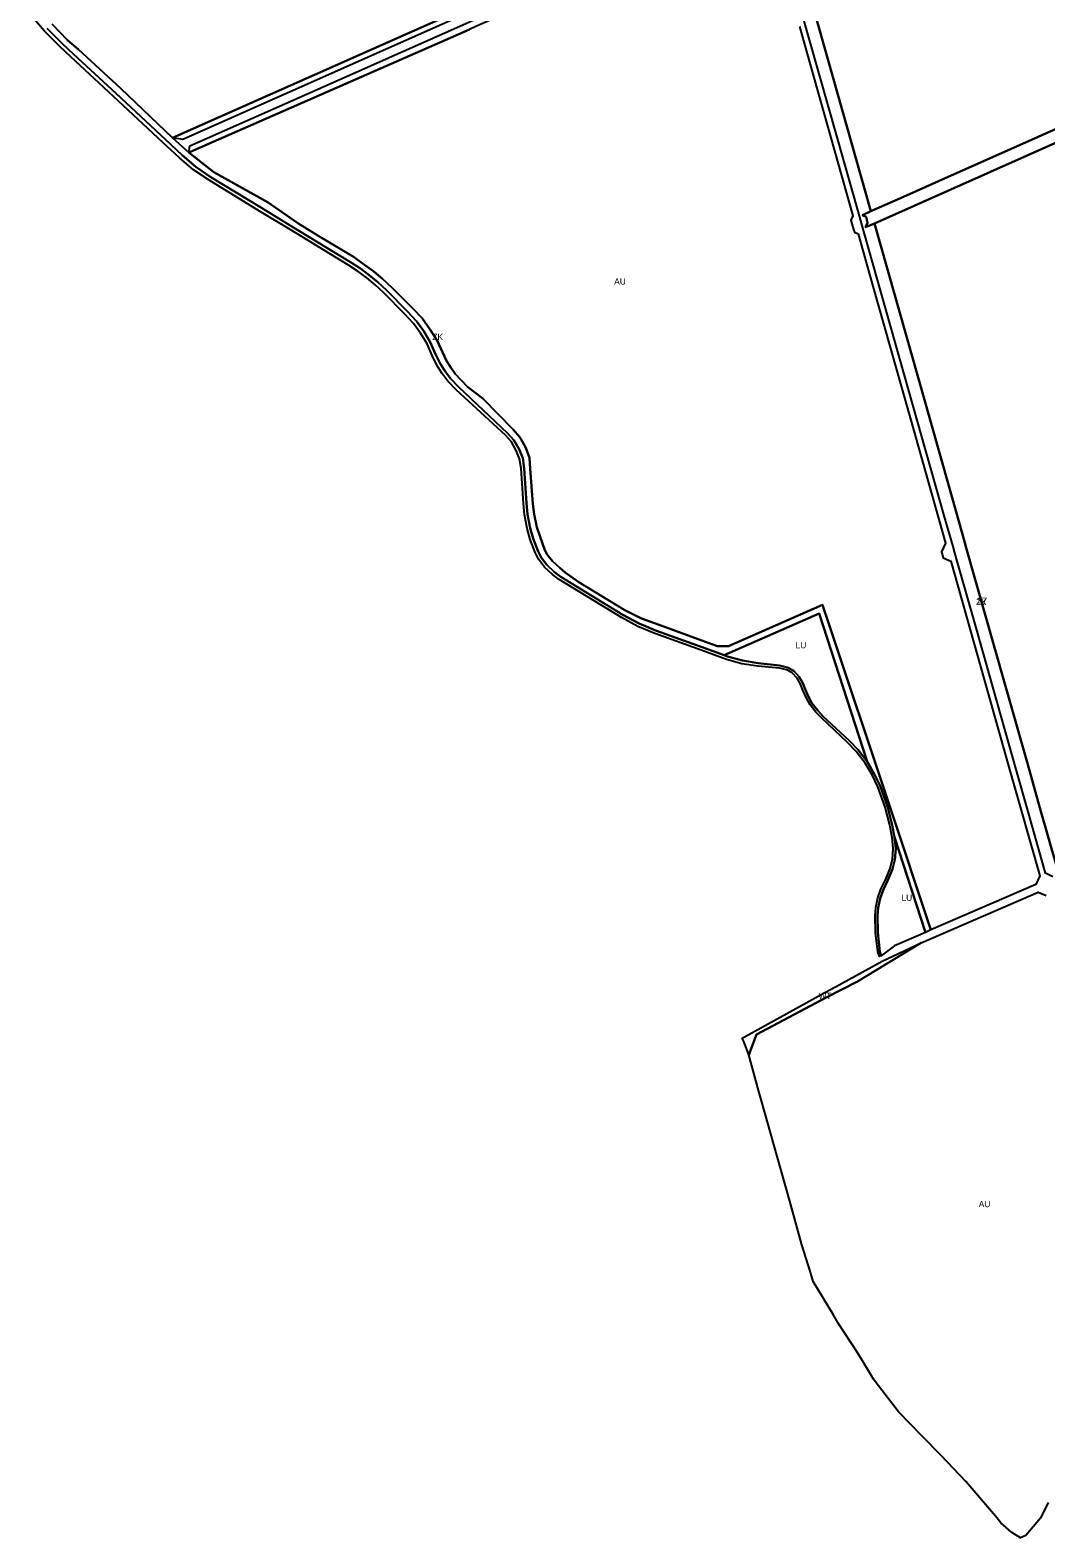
# Model space of a CAD drawing. Extents: x -522079 to -518833, y -1142398 to -1139961.
# Drawn here: x -521819 to -521003, y -1142398 to -1141186 of the extents above; entities that cross this region are included whole.
import ezdxf

# ---------------------------------------------------------------- set-up
doc = ezdxf.new("R2010")
doc.units = 0
for name, color, linetype in [('90640013', 7, 'Continuous'), ('90710013', 7, 'Continuous'), ('90710023', 7, 'Continuous'), ('90750013', 7, 'Continuous'), ('90770013', 7, 'Continuous'), ('ID_navrh', 7, 'Continuous')]:
    doc.layers.add(name, color=color, linetype=linetype)

msp = doc.modelspace()

# ---------------------------------------------------------------- linework, layer by layer
at = {"layer": '90640013'}
msp.add_lwpolyline([(-521805.87, -1141184.18), (-521793.6, -1141196.53), (-521784.67, -1141204.85), (-521750.42, -1141236.56), (-521710.79, -1141273.6), (-521697.27, -1141286.12), (-521686.23, -1141295.55), (-521674.08, -1141303.65), (-521633.59, -1141328.38), (-521608.95, -1141343.32), (-521561.83, -1141372.1), (-521553.85, -1141377.26), (-521546.79, -1141382.47), (-521539.97, -1141388.19), (-521532.97, -1141394.62), (-521516.02, -1141411.74), (-521508.94, -1141419.63), (-521503.06, -1141427.66), (-521497.72, -1141436.55), (-521493.43, -1141445.97), (-521489.81, -1141453.49), (-521485.96, -1141459.56), (-521481.44, -1141465.72), (-521474.82, -1141472.48), (-521435.7, -1141509.5), (-521430.56, -1141515.15), (-521426.4, -1141522.52), (-521423.45, -1141529.64), (-521422.3, -1141537.87), (-521420.36, -1141565.98), (-521419.55, -1141574.63), (-521417.39, -1141585.84), (-521415, -1141594.31), (-521411.13, -1141604.62), (-521408.6, -1141609.5), (-521404.06, -1141615.52), (-521397.79, -1141621.36), (-521392.9, -1141624.99), (-521342.84, -1141655.56), (-521329.77, -1141662.64), (-521315.94, -1141668.52), (-521279.18, -1141681.72), (-521261.42, -1141688.16), (-521258.87, -1141689.08), (-521246.75, -1141692.49), (-521234.23, -1141694.42), (-521216.85, -1141696.44), (-521210.58, -1141697.9), (-521205.36, -1141700.71), (-521201.07, -1141705.38), (-521198.1, -1141710.58), (-521196.27, -1141715.36), (-521193.87, -1141721.1), (-521191.06, -1141726.58), (-521186.22, -1141732.52), (-521181.74, -1141737.31), (-521160.88, -1141756.78), (-521153.73, -1141764.26), (-521146.44, -1141773.64), (-521140.73, -1141783.35), (-521136, -1141793.25), (-521130, -1141809.79), (-521126.54, -1141823.43), (-521124.58, -1141834.32), (-521123.46, -1141843.47), (-521124.12, -1141852.65), (-521126.12, -1141860.01), (-521130.11, -1141869.48), (-521133.7, -1141876.9), (-521136.12, -1141883.81), (-521137.56, -1141891.19), (-521138.09, -1141897.36), (-521137.83, -1141911.01), (-521136.31, -1141926.58), (-521135.11, -1141929.87), (-521136.46, -1141930.46), (-521137.86, -1141926.67), (-521139.81, -1141911.29), (-521140.05, -1141897.31), (-521139.56, -1141890.84), (-521138.03, -1141883.29), (-521135.49, -1141876.13), (-521131.82, -1141868.6), (-521127.98, -1141859.55), (-521126.1, -1141852.28), (-521125.45, -1141843.51), (-521126.47, -1141834.73), (-521128.54, -1141823.8), (-521131.96, -1141810.32), (-521137.85, -1141793.99), (-521142.46, -1141784.23), (-521148.13, -1141774.78), (-521155.26, -1141765.5), (-521162.29, -1141758.22), (-521183.03, -1141738.83), (-521187.74, -1141733.86), (-521192.28, -1141728.07), (-521195.55, -1141722.03), (-521198.13, -1141716.1), (-521199.97, -1141711.28), (-521202.67, -1141706.57), (-521206.66, -1141702.29), (-521211.3, -1141699.75), (-521216.85, -1141698.47), (-521234.47, -1141696.96), (-521247.24, -1141694.95), (-521259.69, -1141691.44), (-521280.03, -1141684.05), (-521317.08, -1141670.75), (-521330.81, -1141664.89), (-521344.1, -1141657.73), (-521394.19, -1141627.12), (-521399.42, -1141623.32), (-521405.95, -1141617.2), (-521410.67, -1141610.84), (-521413.41, -1141605.57), (-521417.34, -1141595.15), (-521419.85, -1141586.36), (-521421.99, -1141574.92), (-521422.84, -1141566.15), (-521424.81, -1141537.99), (-521425.94, -1141530.31), (-521428.59, -1141523.58), (-521432.52, -1141516.64), (-521437.41, -1141511.31), (-521476.9, -1141474.65), (-521483.59, -1141467.79), (-521488.42, -1141461.33), (-521492.43, -1141454.93), (-521496.24, -1141447.12), (-521500.39, -1141437.89), (-521505.54, -1141429.29), (-521511.22, -1141421.52), (-521518.22, -1141413.8), (-521535.13, -1141396.73), (-521541.97, -1141390.39), (-521548.66, -1141384.81), (-521555.61, -1141379.71), (-521563.41, -1141374.64), (-521610.54, -1141345.88), (-521635.13, -1141330.98), (-521675.66, -1141306.27), (-521688.05, -1141297.92), (-521699.37, -1141288.32), (-521712.83, -1141275.84), (-521752.44, -1141238.81), (-521786.69, -1141207.07), (-521795.61, -1141198.73), (-521808.03, -1141186.29), (-521819.49, -1141173.11)], dxfattribs=at)
msp.add_lwpolyline([(-521241.65, -1142009.35), (-521245.74, -1141998.54), (-521247.07, -1141995.86), (-521180.62, -1141959.39), (-521171.94, -1141954.7), (-521134.44, -1141933.97), (-521103.17, -1141919.44), (-521154.29, -1141950.51), (-521178.81, -1141962.98), (-521235.48, -1141993.03)], close=True, dxfattribs=at)
at = {"layer": '90710013'}
for points in [[(-521801.69, -1141180.84), (-521789.46, -1141193.57), (-521780.54, -1141201.02), (-521746.52, -1141232.38), (-521705, -1141272.16), (-521692.02, -1141284.07), (-521671.77, -1141299.69), (-521628.15, -1141324.02), (-521604.24, -1141340.75), (-521587.36, -1141351.16), (-521558.92, -1141368.2), (-521557.71, -1141369.1), (-521550.74, -1141374.27), (-521543.06, -1141379.52), (-521536.29, -1141385.49), (-521528.31, -1141392.77), (-521511.47, -1141409.59), (-521504.19, -1141417.07), (-521498.23, -1141425.96), (-521492.17, -1141435.06), (-521488.03, -1141444.36), (-521484.69, -1141451.44), (-521481.18, -1141456.84), (-521477.75, -1141461.99), (-521467.85, -1141472.41), (-521455.62, -1141481.81), (-521431.09, -1141506.63), (-521426.04, -1141512.48), (-521425.07, -1141514.17), (-521421, -1141521.26), (-521418.07, -1141529.55), (-521417.47, -1141538.2), (-521415.34, -1141566.3), (-521414.13, -1141574.69), (-521412.01, -1141585.06), (-521409.49, -1141593.05), (-521406.05, -1141602.85), (-521404.05, -1141606.86), (-521399.61, -1141612.42), (-521393.54, -1141617.98), (-521389.3, -1141621.72), (-521378.39, -1141629.5), (-521341.44, -1141652.02), (-521328.02, -1141658.46), (-521313.67, -1141663.71), (-521277.4, -1141677.06), (-521266.74, -1141680.79), (-521257.85, -1141680.84), (-521182.3, -1141647.66), (-521180.65, -1141652.62), (-521178.83, -1141658.1), (-521128.33, -1141809.83), (-521095.32, -1141908.99), (-521099.58, -1141911), (-521124.58, -1141834.32), (-521126.54, -1141823.43), (-521130, -1141809.79), (-521136, -1141793.25), (-521140.73, -1141783.35), (-521146.44, -1141773.64), (-521185.06, -1141654.56), (-521261.42, -1141688.16), (-521279.18, -1141681.72), (-521315.94, -1141668.52), (-521329.77, -1141662.64), (-521342.84, -1141655.56), (-521392.9, -1141624.99), (-521397.79, -1141621.36), (-521404.06, -1141615.52), (-521408.6, -1141609.5), (-521411.13, -1141604.62), (-521415, -1141594.31), (-521417.39, -1141585.84), (-521419.55, -1141574.63), (-521420.36, -1141565.98), (-521422.3, -1141537.87), (-521423.45, -1141529.64), (-521426.4, -1141522.52), (-521430.56, -1141515.15), (-521435.7, -1141509.5), (-521474.82, -1141472.48), (-521481.44, -1141465.72), (-521485.96, -1141459.56), (-521489.81, -1141453.49), (-521493.43, -1141445.97), (-521497.72, -1141436.55), (-521503.06, -1141427.66), (-521508.94, -1141419.63), (-521516.02, -1141411.74), (-521532.97, -1141394.62), (-521539.97, -1141388.19), (-521546.79, -1141382.47), (-521553.85, -1141377.26), (-521561.83, -1141372.1), (-521608.95, -1141343.32), (-521633.59, -1141328.38), (-521674.08, -1141303.65), (-521686.23, -1141295.55), (-521697.27, -1141286.12), (-521710.79, -1141273.6), (-521750.42, -1141236.56), (-521784.67, -1141204.85), (-521793.6, -1141196.53), (-521805.87, -1141184.18)], [(-520895.18, -1141231.65), (-521140.66, -1141340.91), (-521147.68, -1141344.03), (-521146.08, -1141340.6), (-521147.33, -1141335.67), (-521150.33, -1141334.27), (-521143.42, -1141331.19), (-521117.38, -1141319.6), (-521081.35, -1141303.56), (-521038.45, -1141284.46), (-520895.96, -1141221.04)]]:
    msp.add_lwpolyline(points, dxfattribs=at)
at = {"layer": '90710023'}
for points in [[(-521134.23, -1141020.21), (-521134.18, -1141024.63), (-521223.67, -1141064.26), (-521262.72, -1141081.47), (-521271.86, -1141085.49), (-521354.37, -1141121.84), (-521464.85, -1141170.68), (-521478.81, -1141176.87), (-521531.28, -1141200.09), (-521696.71, -1141273.51), (-521705, -1141272.16), (-521476.67, -1141170.91), (-521472.07, -1141168.66), (-521274.53, -1141082.16), (-521271.3, -1141080.74)], [(-521692.02, -1141284.07), (-521691.15, -1141278.7), (-521609.81, -1141242.59), (-521474.13, -1141182.35), (-521460.33, -1141176.23), (-521405.94, -1141152.24), (-521236.08, -1141077.32), (-521230.09, -1141080.11), (-521461.21, -1141182.74), (-521466.3, -1141184.96)]]:
    msp.add_lwpolyline(points, close=True, dxfattribs=at)
for points in [[(-521216.29, -1141073.97), (-521143.42, -1141331.19), (-521150.33, -1141334.27), (-521147.33, -1141335.67), (-521146.08, -1141340.6), (-521147.68, -1141344.03), (-521140.66, -1141340.91), (-521100.48, -1141482.76), (-521074.97, -1141572.8), (-521068.18, -1141596.78), (-521066.79, -1141601.67), (-521035.75, -1141711.23), (-521017.38, -1141776.07), (-521007.52, -1141810.87), (-520993.82, -1141859.25)], [(-520997.06, -1141866.15), (-521003.04, -1141863.38), (-521016.76, -1141814.92), (-521026.62, -1141780.12), (-521044.98, -1141715.3), (-521058.67, -1141667), (-521074.66, -1141610.52), (-521076.03, -1141605.72), (-521077.42, -1141600.82), (-521078.78, -1141596.05), (-521084.21, -1141576.91), (-521109.72, -1141486.85), (-521149.23, -1141347.36), (-521150.52, -1141342.71), (-521151.86, -1141337.89), (-521153.24, -1141332.9), (-521177.35, -1141247.92), (-521225.53, -1141078.04)]]:
    msp.add_lwpolyline(points, dxfattribs=at)
at = {"layer": '90750013'}
for points in [[(-520727.16, -1141148.38), (-520890.16, -1141218.54), (-520895.96, -1141221.04), (-521038.45, -1141284.46), (-521081.35, -1141303.56), (-521117.38, -1141319.6), (-521143.42, -1141331.19), (-521216.29, -1141073.97), (-521190.59, -1141062.63), (-521154.28, -1141046.62), (-521111.47, -1141027.75), (-521085.77, -1141016.42), (-520964.29, -1140970.32), (-520959.78, -1140968.46), (-520892.3, -1140942.89), (-520888.93, -1140954.41), (-520885.58, -1140965.84), (-520881.52, -1140979.72), (-520872.93, -1141009.05), (-520861.45, -1141049.84), (-520847.24, -1141100.33), (-520846.14, -1141104.23), (-520733.88, -1141082.24)], [(-520993.82, -1141859.25), (-521007.52, -1141810.87), (-521017.38, -1141776.07), (-521035.75, -1141711.23), (-521066.79, -1141601.67), (-521068.18, -1141596.78), (-521074.97, -1141572.8), (-521100.48, -1141482.76), (-521140.66, -1141340.91), (-520895.18, -1141231.65), (-520856.02, -1141374.46), (-520831.3, -1141464.59), (-520824.77, -1141488.43), (-520824.28, -1141488.21), (-520821.3, -1141482.16), (-520819.82, -1141495.44), (-520822.47, -1141493.04), (-520824.63, -1141494.01), (-520852.89, -1141630.48), (-520869.65, -1141711.4), (-520878.55, -1141754.38), (-520890.85, -1141813.79)]]:
    msp.add_lwpolyline(points, close=True, dxfattribs=at)
for points in [[(-521476.67, -1141170.91), (-521705, -1141272.16), (-521746.52, -1141232.38), (-521780.54, -1141201.02), (-521789.46, -1141193.57), (-521801.69, -1141180.84)], [(-521201.01, -1141182.77), (-521192.96, -1141211.21), (-521157.91, -1141334.94), (-521159.51, -1141338.32), (-521158.68, -1141341.24), (-521157.35, -1141345.97), (-521156.76, -1141348.04), (-521153.82, -1141349.39), (-521142.48, -1141389.44), (-521107.96, -1141511.35), (-521083.41, -1141598.05), (-521086.66, -1141604.9), (-521085.26, -1141609.76), (-521079.3, -1141612.54), (-521031.39, -1141781.75), (-521007.67, -1141865.49), (-521010.77, -1141872.32), (-521095.32, -1141908.99), (-521128.33, -1141809.83), (-521178.83, -1141658.1), (-521180.65, -1141652.62), (-521182.3, -1141647.66), (-521257.85, -1141680.84), (-521266.74, -1141680.79), (-521277.4, -1141677.06), (-521313.67, -1141663.71), (-521328.02, -1141658.46), (-521341.44, -1141652.02), (-521378.39, -1141629.5), (-521389.3, -1141621.72), (-521393.54, -1141617.98), (-521399.61, -1141612.42), (-521404.05, -1141606.86), (-521406.05, -1141602.85), (-521409.49, -1141593.05), (-521412.01, -1141585.06), (-521414.13, -1141574.69), (-521415.34, -1141566.3), (-521417.47, -1141538.2), (-521418.07, -1141529.55), (-521421, -1141521.26), (-521425.07, -1141514.17), (-521426.04, -1141512.48), (-521431.09, -1141506.63), (-521455.62, -1141481.81), (-521467.85, -1141472.41), (-521477.75, -1141461.99), (-521481.18, -1141456.84), (-521484.69, -1141451.44), (-521488.03, -1141444.36), (-521492.17, -1141435.06), (-521498.23, -1141425.96), (-521504.19, -1141417.07), (-521511.47, -1141409.59), (-521528.31, -1141392.77), (-521536.29, -1141385.49), (-521543.06, -1141379.52), (-521550.74, -1141374.27), (-521557.71, -1141369.1), (-521558.92, -1141368.2), (-521587.36, -1141351.16), (-521604.24, -1141340.75), (-521628.15, -1141324.02), (-521671.77, -1141299.69), (-521692.02, -1141284.07), (-521466.3, -1141184.96)], [(-521000.81, -1142369.28), (-521007.1, -1142381.81), (-521018.9, -1142395.87), (-521023.14, -1142397.72), (-521030.26, -1142393.33), (-521039.1, -1142385.71), (-521043.28, -1142380.16), (-521067.07, -1142352.38), (-521086.87, -1142331.63), (-521102.18, -1142315.9), (-521121.26, -1142296.3), (-521140.11, -1142271.9), (-521141.26, -1142270.03), (-521148.58, -1142258.19), (-521154.1, -1142249.25), (-521169.79, -1142225.11), (-521174.19, -1142217.64), (-521189.97, -1142191.57), (-521192.34, -1142183.35), (-521198.94, -1142162.11), (-521208.63, -1142126.99), (-521218.49, -1142092.03), (-521226.84, -1142062.52), (-521233.47, -1142038.91), (-521241.65, -1142009.35), (-521235.48, -1141993.03), (-521178.81, -1141962.98), (-521154.29, -1141950.51), (-521103.17, -1141919.44), (-521009, -1141878.54), (-521002.46, -1141881.16)]]:
    msp.add_lwpolyline(points, dxfattribs=at)
at = {"layer": '90770013'}
for points in [[(-521146.44, -1141773.64), (-521153.73, -1141764.26), (-521160.88, -1141756.78), (-521181.74, -1141737.31), (-521186.22, -1141732.52), (-521191.06, -1141726.58), (-521193.87, -1141721.1), (-521196.27, -1141715.36), (-521198.1, -1141710.58), (-521201.07, -1141705.38), (-521205.36, -1141700.71), (-521210.58, -1141697.9), (-521216.85, -1141696.44), (-521234.23, -1141694.42), (-521246.75, -1141692.49), (-521258.87, -1141689.08), (-521261.42, -1141688.16), (-521185.06, -1141654.56)], [(-521099.58, -1141911), (-521124.47, -1141921.72), (-521135.11, -1141929.87), (-521136.31, -1141926.58), (-521137.83, -1141911.01), (-521138.09, -1141897.36), (-521137.56, -1141891.19), (-521136.12, -1141883.81), (-521133.7, -1141876.9), (-521130.11, -1141869.48), (-521126.12, -1141860.01), (-521124.12, -1141852.65), (-521123.46, -1141843.47), (-521124.58, -1141834.32)]]:
    msp.add_lwpolyline(points, close=True, dxfattribs=at)

# ---------------------------------------------------------------- texts
at = {"layer": '90640013'}
msp.add_text('WT', height=5, rotation=0, dxfattribs=at).set_placement((-521185.609, -1141964.395))
at = {"layer": '90710013'}
msp.add_text('ZK', height=5, rotation=360, dxfattribs=at).set_placement((-521496.07, -1141434.688))
at = {"layer": '90710023'}
msp.add_text('ZK', height=5, rotation=0, dxfattribs=at).set_placement((-521058.915, -1141647.8))
at = {"layer": '90750013'}
for p in [(-521349.845, -1141390.093), (-521056.745, -1142131.857)]:
    msp.add_text('AU', height=5, rotation=0, dxfattribs=at).set_placement(p)
at = {"layer": '90770013'}
for p in [(-521203.93, -1141682.565), (-521118.835, -1141885.617)]:
    msp.add_text('LU', height=5, rotation=360, dxfattribs=at).set_placement(p)
at = {"layer": 'ID_navrh'}
msp.add_text('17', height=6, rotation=0, dxfattribs=at).set_placement((-521058.915, -1141647.8))

doc.saveas('drawing.dxf')
